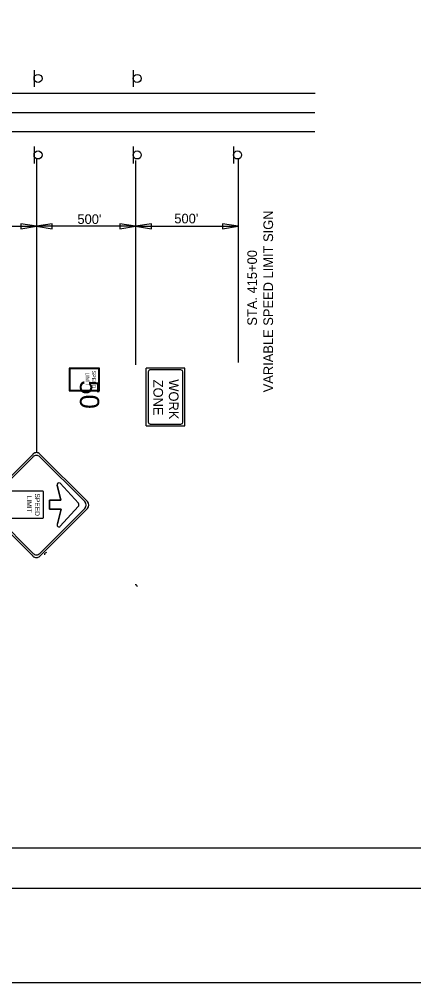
# Model space of a CAD drawing. Extents: x 2155255 to 2162649, y 140388 to 141878.
# Drawn here: x 2156964 to 2157209, y 140388 to 140988 of the extents above; entities that cross this region are included whole.
import ezdxf

# ---------------------------------------------------------------- set-up
doc = ezdxf.new("R2010")
doc.units = 0
for name, color, linetype in [('5', 7, 'Continuous'), ('Default', 7, 'Continuous'), ('PR_Dimensions1', 7, 'Continuous'), ('PR_Traffic_Control_Devices_Temp', 7, 'Continuous'), ('PR_Traffic_Temp_Txt', 7, 'Continuous'), ('SHT_Plot_Shape_Full', 7, 'Continuous'), ('SHT_Plot_Shape_Half', 7, 'Continuous'), ('SHT_Sheet_Border', 7, 'Continuous'), ('TOPO_Asphalt', 7, 'Continuous')]:
    doc.layers.add(name, color=color, linetype=linetype)

# ---------------------------------------------------------------- blocks, each defined once
blk = doc.blocks.new('R2-1e')
at = {"layer": 'Default'}
for p, q in [((3, 4), (0, 4)), ((0, 4), (0, 0)), ((0.1, 3.81), (0.1, 0.19)), ((2.81, 3.9), (0.19, 3.9)), ((2.9, 0.19), (2.9, 3.81)), ((3, 0), (3, 4)), ((0, 0), (3, 0)), ((0.19, 0.1), (2.81, 0.1))]:
    blk.add_line(p, q, dxfattribs=at)
for centre, start, end in [((0.19, 3.81), 90, 180), ((2.81, 3.81), 0, 90), ((0.19, 0.19), 180, 270), ((2.81, 0.19), 270, 0)]:
    blk.add_arc(centre, 0.0875, start, end, dxfattribs=at)
for s, p in [('SPEED', (0.33, 3)), ('LIMIT', (0.57, 2.17))]:
    blk.add_text(s, height=0.5, dxfattribs=at).set_placement(p)
blk = doc.blocks.new('CS-14E')
at = {"layer": 'Default'}
for p, q in [((7.62, 2.54), (0, 2.54)), ((0, 2.54), (0, -2.54)), ((0.25, 2.06), (0.25, -2.06)), ((7.14, 2.29), (0.48, 2.29)), ((7.37, -2.06), (7.37, 2.06)), ((7.62, -2.54), (7.62, 2.54)), ((7.62, -2.54), (0, -2.54)), ((0.48, -2.29), (7.14, -2.29))]:
    blk.add_line(p, q, dxfattribs=at)
for centre, start, end in [((0.48, 2.06), 90, 180), ((7.14, 2.06), 0, 90), ((0.48, -2.06), 180, 270), ((7.14, -2.06), 270, 0)]:
    blk.add_arc(centre, 0.222, start, end, dxfattribs=at)
for s, p in [('WORK', (1.48, 0.44)), ('ZONE', (1.53, -1.6))]:
    blk.add_text(s, height=1.27, dxfattribs=at).set_placement(p)
blk = doc.blocks.new('TCSIGN')
at = {"layer": 'Default'}
blk.add_line((5.26, 2.5), (-5.26, 2.5), dxfattribs=at)
blk.add_circle((0, 0), 2.5, dxfattribs=at)
blk = doc.blocks.new('Arrowhd')
at = {"layer": 'Default'}
blk.add_lwpolyline([(0.318, -0.053), (0.318, 0.053), (0, 0)], close=True, dxfattribs=at)
blk = doc.blocks.new('W3-5_1')
at = {"layer": '5'}
for p, q in [((0.81, 7.63), (6.73, 13.56)), ((13.56, 7.63), (7.63, 13.56)), ((6.73, 0.81), (0.81, 6.74)), ((7.63, 0.81), (13.56, 6.74))]:
    blk.add_line(p, q, dxfattribs=at)
for centre, start, end in [((7.18, 13.11), 45, 135), ((1.26, 7.18), 135, 225), ((13.11, 7.18), 315, 45), ((7.18, 1.26), 225, 315)]:
    blk.add_arc(centre, 0.635, start, end, dxfattribs=at)
at = {"layer": 'Default'}
for p, q in [((0.45, 7.63), (6.73, 13.92)), ((6.95, 12.72), (4.28, 10.3)), ((13.92, 7.63), (7.63, 13.92)), ((9.98, 10.32), (7.37, 12.69)), ((5.35, 8.02), (5.35, 3.42)), ((8.8, 8.13), (5.46, 8.13)), ((8.91, 3.42), (8.91, 8.02)), ((6.73, 0.45), (0.45, 6.74)), ((7.63, 0.45), (13.92, 6.74)), ((5.46, 3.3), (8.8, 3.3))]:
    blk.add_line(p, q, dxfattribs=at)
for points in [[(4.28, 10.3), (6.95, 12.72)], [(7.37, 12.69), (9.98, 10.32)], [(4.58, 9.92), (6.55, 10.41), (6.55, 8.91), (7.74, 8.91), (7.74, 10.45), (9.68, 9.96)], [(9.68, 9.96), (7.74, 10.45), (7.74, 8.91), (6.55, 8.91), (6.55, 10.41), (4.58, 9.92)]]:
    blk.add_lwpolyline(points, dxfattribs=at)
for centre, radius, start, end in [((7.18, 13.47), 0.635, 45, 135), ((7.14, 12.51), 0.285, 37.9142, 132.1493), ((7.14, 12.51), 0.285, 37.9142, 132.1493), ((4.52, 10.19), 0.269, 154.0903, 283.9085), ((4.52, 10.19), 0.269, 154.0903, 283.9085), ((9.83, 10.15), 0.237, 231.3417, 47.9123), ((9.83, 10.15), 0.237, 231.3417, 47.9123), ((0.9, 7.18), 0.635, 135, 225), ((5.46, 8.02), 0.111, 90, 180), ((8.8, 8.02), 0.111, 0, 90), ((13.47, 7.18), 0.635, 315, 45), ((5.46, 3.42), 0.111, 180, 270), ((8.8, 3.42), 0.111, 270, 0), ((7.18, 0.9), 0.635, 225, 315)]:
    blk.add_arc(centre, radius, start, end, dxfattribs=at)
for s, p in [('SPEED', (5.65, 6.99)), ('LIMIT', (5.95, 5.93))]:
    blk.add_text(s, height=0.635, dxfattribs=at).set_placement(p)

msp = doc.modelspace()

# ---------------------------------------------------------------- linework, layer by layer
at = {"layer": 'Default'}
for centre, start, end in [((2156980.63, 140654.73), 90, 180), ((2157035.88, 140634.7), 360, 90)]:
    msp.add_arc(centre, 1.33, start, end, dxfattribs=at)
at = {"layer": 'PR_Dimensions1'}
for p, q in [((2156974.31, 140900.91), (2156974.31, 140718.32)), ((2157036.1, 140900.19), (2157036.1, 140772.95)), ((2157100.04, 140901.63), (2157100.04, 140774.39)), ((2156920.31, 140859.25), (2156974.31, 140859.25)), ((2157036.1, 140859.25), (2156974.31, 140859.25)), ((2157036.1, 140859.25), (2157100.04, 140859.25))]:
    msp.add_line(p, q, dxfattribs=at)
at = {"layer": 'SHT_Plot_Shape_Full'}
msp.add_lwpolyline([(2156155.34, 141588.17), (2157955.34, 141588.17), (2157955.34, 140388.17), (2156155.34, 140388.17)], close=True, dxfattribs=at)
at = {"layer": 'SHT_Plot_Shape_Half'}
msp.add_lwpolyline([(2156237.22, 141546.92), (2157937.22, 141546.92), (2157937.22, 140446.92), (2156237.22, 140446.92)], close=True, dxfattribs=at)
at = {"layer": 'SHT_Sheet_Border'}
msp.add_lwpolyline([(2157909.72, 140471.92), (2156334.72, 140471.92), (2156334.72, 141521.92), (2157909.72, 141521.92)], close=True, dxfattribs=at)
at = {"layer": 'TOPO_Asphalt'}
for p, q in [((2157147.83, 140941.97), (2156447.24, 140941.97)), ((2157147.76, 140929.97), (2156447.37, 140929.97)), ((2157147.69, 140917.97), (2156447.51, 140917.97)), ((2157147.69, 140917.97), (2156447.51, 140917.97))]:
    msp.add_line(p, q, dxfattribs=at)

# ---------------------------------------------------------------- block references
at = {"layer": 'PR_Dimensions1', "xscale": 30.761459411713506, "yscale": 30.761459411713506, "rotation": 180}
for p in [(2156974.31, 140859.25), (2157036.1, 140859.25), (2157100.04, 140859.25)]:
    msp.add_blockref('Arrowhd', p, dxfattribs=at)
at = {"layer": 'PR_Dimensions1', "xscale": 30.761459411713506, "yscale": 30.761459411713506}
for p in [(2156974.31, 140859.25), (2157036.1, 140859.25)]:
    msp.add_blockref('Arrowhd', p, dxfattribs=at)
at = {"layer": 'PR_Traffic_Control_Devices_Temp', "rotation": 89.99999999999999}
for p in [(2156975.29, 140951.31), (2157037.08, 140951.31), (2156975.29, 140903.66), (2157037.08, 140903.66), (2157099.58, 140903.66)]:
    msp.add_blockref('TCSIGN', p, dxfattribs=at)
at = {"layer": 'PR_Traffic_Control_Devices_Temp', "rotation": -90.00000000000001}
for name, p, xscale, yscale in [('R2-1e', (2156994.73, 140770.94), 4.7244, 4.7244), ('CS-14E', (2157054.73, 140770.94), 4.7244, 4.7244), ('W3-5_1', (2156940.39, 140719.56), 4.72, 4.72)]:
    msp.add_blockref(name, p, dxfattribs=dict(at, xscale=xscale, yscale=yscale))

# ---------------------------------------------------------------- texts
at = {"layer": 'PR_Traffic_Control_Devices_Temp'}
msp.add_text('50', height=12, rotation=270, dxfattribs=at).set_placement((2157001.41, 140763.4))
at = {"layer": 'PR_Traffic_Temp_Txt'}
for s, rotation, p in [('VARIABLE SPEED LIMIT SIGN', 90, (2157121.7, 140755.85)), ("500'", 360, (2156999.84, 140860.7)), ("500'", 360, (2157060.2, 140861.07)), ('STA. 415+00', 90, (2157111.68, 140797.37))]:
    msp.add_text(s, height=6, rotation=rotation, dxfattribs=at).set_placement(p)

doc.saveas('drawing.dxf')
